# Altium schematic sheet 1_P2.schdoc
size 426 x 304 mm
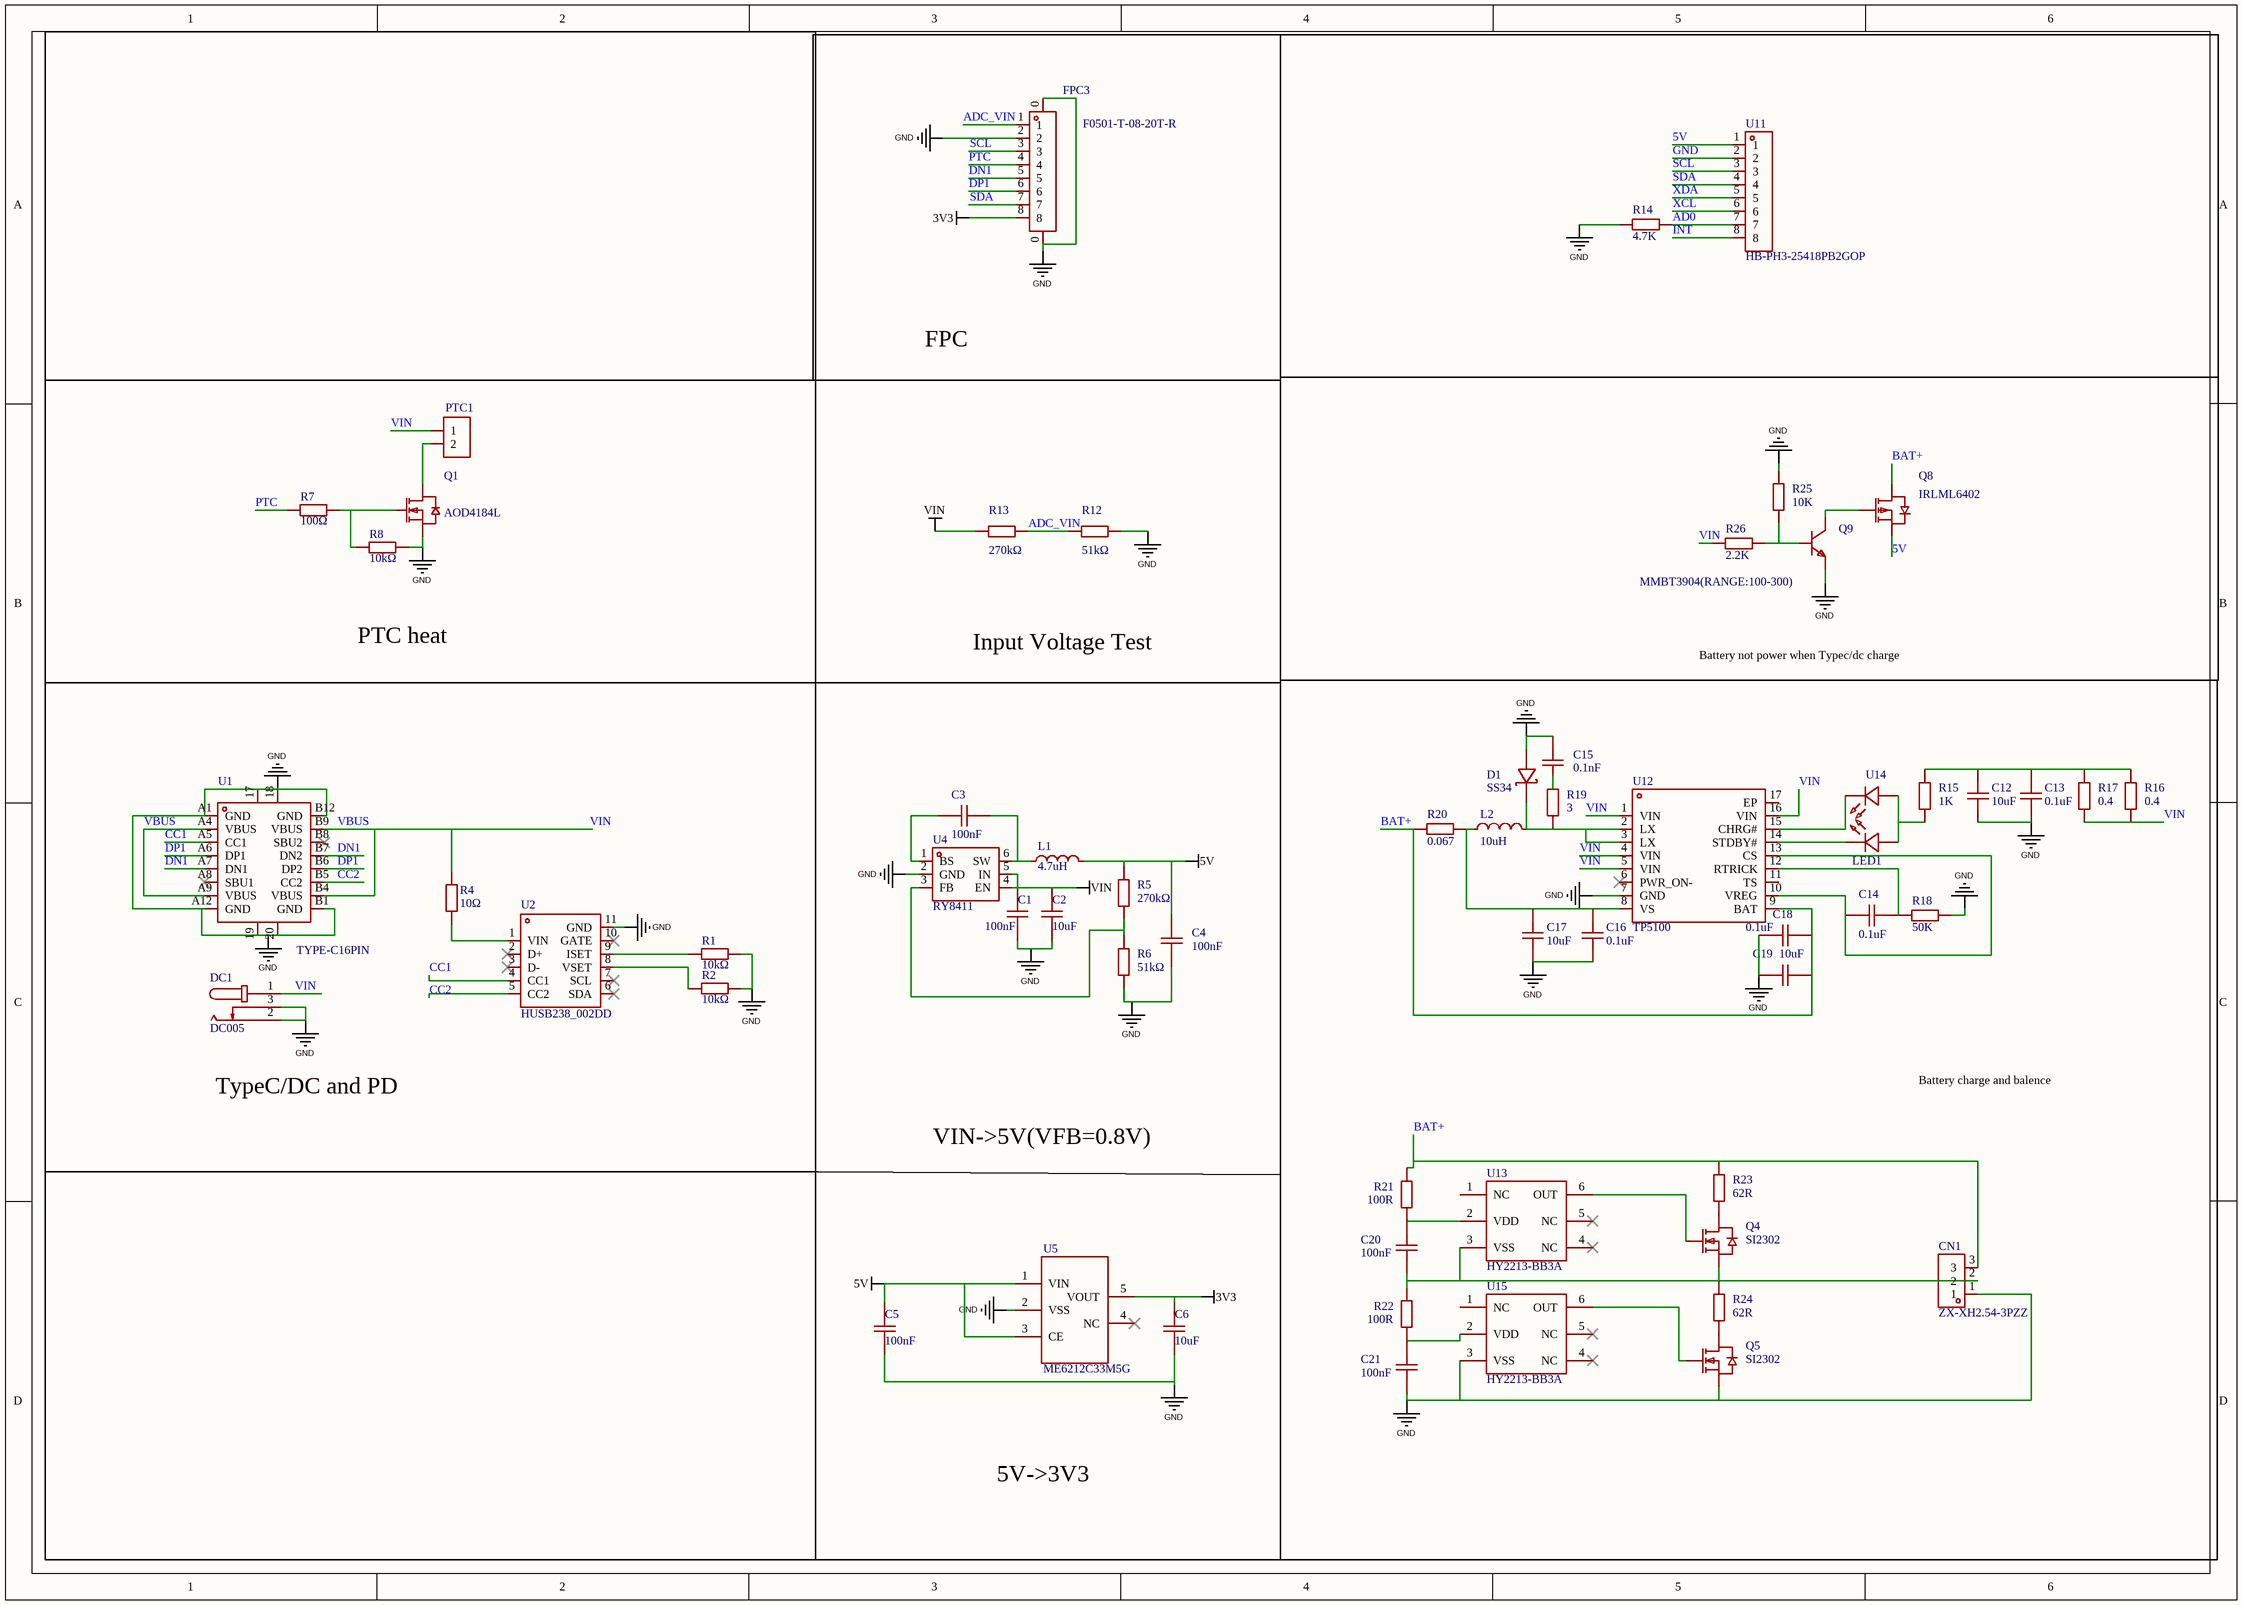
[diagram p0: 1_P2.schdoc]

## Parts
C1  100nF  [C0603]
C2  10uF  [C0603]
C3  100nF  [C0603]
C4  100nF  [C0603]
C5  100nF  [C0603]
C6  10uF  [C0603]
C12  10uF  [C0603]
C13  0.1uF  [C0603]
C14  0.1uF  [C0603]
C15  0.1nF  [C0603]
C16  0.1uF  [C0603]
C17  10uF  [C0603]
C18  0.1uF  [C0603]
C19  10uF  [C0603]
C20  100nF  [C0603]
C21  100nF  [C0603]
CN1  ZX-XH2.54-3PZZ  [CONN-TH_3P-P2.54_2501S-3P]
D1  SS34  [SMA_L4.3-W2.6-LS5.2-RD]
DC1  DC005  [DC-IN-TH_DC005]
FPC3  F0501-T-08-20T-R  [FPC-SMD_8P-P0.50_L4.4-W9.6]
L1  4.7uH  [IND-SMD_L3.5-W3.0]
L2  10uH  [L0603]
LED1  XL-1608SURC-06  [LED0603-RD_RED]  (value not drawn)
PTC1  (no value)  [HDR-TH_2P-P2.54-V-F]
Q1  AOD4184L  [TO-252-2_L6.6-W6.1-P4.57-LS9.9-TL-CW]
Q4  SI2302  [SOT-23-3_L2.9-W1.3-P1.90-LS2.4-BR]
Q5  SI2302  [SOT-23-3_L2.9-W1.3-P1.90-LS2.4-BR]
Q8  IRLML6402  [SOT-23-3_L2.9-W1.3-P1.90-LS2.4-BR]
Q9  MMBT3904(RANGE:100-300)  [SOT-23-3_L2.9-W1.3-P1.90-LS2.4-BR]
R1  10kΩ  [R0603]
R2  10kΩ  [R0603]
R4  10Ω  [R0603]
R5  270kΩ  [R0603]
R6  51kΩ  [R0603]
R7  100Ω  [R0603]
R8  10kΩ  [R0603]
R12  51kΩ  [R0603]
R13  270kΩ  [R0603]
R14  4.7K  [R0603]
R15  1K  [R0603]
R16  0.4  [R0603]
R17  0.4  [R0603]
R18  50K  [R0603]
R19  3  [R0603]
R20  0.067  [R0603]
R21  100R  [R0603]
R22  100R  [R0603]
R23  62R  [R0603]
R24  62R  [R0603]
R25  10K  [R0603]
R26  2.2K  [R0603]
U1  TYPE-C16PIN  [USB-C-SMD_TYPE-C16PIN]
U2  HUSB238_002DD  [DFN-10_L3.0-W3.0-P0.50-BL-EP2.5]
U4  RY8411  [SOT-23-6_L2.9-W1.6-P0.95-LS2.8-TL]
U5  ME6212C33M5G  [SOT-23-5_L3.0-W1.7-P0.95-LS2.8-BL]
U11  HB-PH3-25418PB2GOP  [HDR-TH_8P-P2.54-V-M]
U12  TP5100  [TQFN-16_L4.0-W4.0-P0.65-BL-EP]
U13  HY2213-BB3A  [SOT-23-6_L2.9-W1.6-P0.95-LS2.8-BR]
U14  42-51/GHC-YW2X2K/3T  [LED-SMD_L1.6-W0.8-FD_GREEN-1]  (value not drawn)
U15  HY2213-BB3A  [SOT-23-6_L2.9-W1.6-P0.95-LS2.8-BR]

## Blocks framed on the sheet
FPC: FPC3
Battery not power when Typec/dc charge: Q8 Q9 R14 R25 R26 U11
PTC heat: PTC1 Q1 R7 R8
Input Voltage Test: R12 R13
TypeC/DC and PD: DC1 R1 R2 R4 U1 U2
Battery charge and balence: C12-C21 CN1 D1 L2 LED1 Q4 Q5 R15-R24 U12-U15

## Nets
3V3: C6.1 FPC3.8 U5.5(VOUT)
5V: C4.1 C5.1 L1.2 Q8.2(S) R5.2 U5.1(VIN) U5.3(CE) U11.1
GND: C1.2 C2.2 C4.2 C5.2 C6.2 C12.1 C13.1 C15.2 C16.1 C17.1 C18.2 C19.2 C21.1 CN1.1 D1.2(A) DC1.2 DC1.3 FPC3.0 FPC3.2 Q1.3(S) Q5.2(S) Q9.2(E) R1.2 R2.2 R6.1 R8.2 R12.2 R14.1 R18.2 R25.2 U1.17 U1.18 U1.19 U1.20 U1.A1(GND) U1.A12(GND) U1.B1(GND) U1.B12(GND) U2.11(GND) U4.2(GND) U5.2(VSS) U11.2 U12.7(GND) U15.3(VSS)
VBUS: C1.1 C2.1 DC1.1 PTC1.1 R4.2 R13.1 R16.1 R17.1 R26.1 U1.A4(VBUS) U1.A9(VBUS) U1.B4(VBUS) U1.B9(VBUS) U4.4(EN) U4.5(IN) U12.1(VIN) U12.4(VIN) U12.5(VIN) U12.16(VIN)  [also labelled VIN]
AD0: R14.2 U11.7
ADC_VIN: FPC3.1 R12.1 R13.2
BAT+: C18.1 C19.1 CN1.3 Q8.3(D) R20.1 R21.2 R23.2 U12.9(BAT)
CC1: U1.A5(CC1) U2.4(CC1)
CC2: U1.B5(CC2) U2.5(CC2)
DN1: FPC3.5 U1.A7(DN1) U1.B7(DN2)
DP1: FPC3.6 U1.A6(DP1) U1.B6(DP2)
INT: U11.8
PTC: FPC3.4 R7.1
SCL: FPC3.3 U11.3
SDA: FPC3.7 U11.4
XCL: U11.6
XDA: U11.5
NetC3_1: C3.1 U4.1(BS)
NetC3_2: C3.2 L1.1 U4.6(SW)
NetC12_2: C12.2 C13.2 R15.2 R16.2 R17.2
NetC14_1: C14.1 U12.10(VREG) U12.13(CS)
NetC14_2: C14.2 R18.1 U12.12(RTRICK)
NetC15_1: C15.1 R19.2
NetC16_2: C16.2 C17.2 L2.1 R20.2 U12.8(VS)
NetC20_1: C20.1 CN1.2 Q4.2(S) R22.2 R24.2 U13.3(VSS)
NetC20_2: C20.2 R21.1 U13.2(VDD)
NetC21_2: C21.2 R22.1 U15.2(VDD)
NetD1_1: D1.1(K) L2.2 R19.1 U12.2(LX) U12.3(LX)
NetLED1_1: LED1.1(K) U12.14(STDBY#)
NetLED1_2: LED1.2(A) R15.1 U14.1(A)
NetPTC1_2: PTC1.2 Q1.2(D)
NetQ1_1: Q1.1(G) R7.2 R8.1
NetQ4_1: Q4.1(G) U13.6(OUT)
NetQ4_3: Q4.3(D) R23.1
NetQ5_1: Q5.1(G) U15.6(OUT)
NetQ5_3: Q5.3(D) R24.1
NetQ8_1: Q8.1(G) Q9.3(C)
NetQ9_1: Q9.1(B) R25.1 R26.2
NetR1_1: R1.1 U2.9(ISET)
NetR2_1: R2.1 U2.8(VSET)
NetR4_1: R4.1 U2.1(VIN)
NetR5_1: R5.1 R6.2 U4.3(FB)
NetU12_15: U12.15(CHRG#) U14.2(C)

Not connected (* = marked no-connect by the designer): U1 A8(SBU1)* B8(SBU2)*; U2 2(D+)* 3(D-)* 6(SDA)* 7(SCL)* 10(GATE)*; U5 4(NC)*; U12 6(PWR_ON-)* 11(TS) 17(EP); U13 1(NC) 4(NC)* 5(NC)*; U15 1(NC) 4(NC)* 5(NC)*

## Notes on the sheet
- VIN->5V(VFB=0.8V)
- 5V->3V3

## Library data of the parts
C1 C3-C5 = CGA0603X7R104K500JT: Manufacturer: HRE(芯声); Symbol: CapAcitance; Add into BOM: yes; Tolerance: ±10%; Voltage Rated: 50V; Temperature Coefficient: X7R
C2 C6 = CL10A106KP8NNNC: Manufacturer: SAMSUNG(三星); Symbol: CapAcitance; Add into BOM: yes; Tolerance: ±10%; Voltage Rated: 10V; Temperature Coefficient: X5R
C12-C21 = CAP_0603: Symbol: CapAcitance; Convert to PCB: yes
CN1 = ZX-XH2.54-3PZZ: Manufacturer: Megastar(兆星); Add into BOM: yes; Pins Structure: 1x3P; Pitch: 2.5mm; Reference Series: XH; Number of PINs Per Row: 3; Rated Current: 3A; Rated Voltage (Max): 250V; Plastic Material: PA66; Flame Retardant Rating: UL94V-0; Z-Height of the Board: 7mm; X-Length of Bottom Edge on Board (Spacing Line): 10mm; Y-Width of Bottom Edge on Board: 5.9mm
D1 = SS34_C8678: Manufacturer: MDD(辰达半导体); Add into BOM: yes; Diode Configuration: 独立式; Forward Voltage (Vf@If): 550mV@3A; Reverse Voltage (Vr): 40V; Rectified Current: 3A; Reverse Leakage Current (Ir): 500uA@40V
DC1 = DC005: Manufacturer: SHOU HAN(首韩); Symbol: DC005_C431533; Add into BOM: yes; Connector Type: DC电源插座; Inside Contact Diameter: 2mm; Outside Contact Diameter: 6.3mm; Current Rating (Max): 500mA; Voltage Rating (Max): 30V
FPC3 = F0501-T-08-20T-R: Manufacturer: XFCN(兴飞); Add into BOM: yes; Locking Feature: 抽屉式; Number of Contacts: 8P; Pitch: 0.5mm
L1 = CD32-4R7M 4.7UH: Manufacturer: DMBJ(振宝佳); Add into BOM: yes; Tolerance: ±20%; Rated Current: 1.5A; DC Resistance (DCR): 137mΩ
L2 = L_0603: Symbol: SDFL1608S100KTF; Add into BOM: yes
LED1 = XL-1608SURC-06: Manufacturer: XINGLIGHT(成兴光); Add into BOM: yes; Illumination Color: 红色; Voltage - Forward(Vf): 2.3V; Power(Watts): 50mW; Forward Current: 20mA; Wavelength - Dominant: 620nm~630nm; Peak Wavelength: 625nm; Lens Color: 无色透明透镜; Luminous Intensity: 225mcd; Viewing Angle: 120°; Mounting Sytle: 正贴
PTC1 = HDR-F_2.54_1x2P: Manufacturer: BOOMELE(博穆精密); Manufacturer Part: 2.54-1*2P母; Symbol: Header-Female-2.54_1x2; Convert to PCB: yes
Q1 = AOD4184L: Manufacturer: AOS; Add into BOM: yes; Type: 1个N沟道; Drain Source Voltage (Vdss): 40V; Continuous Drain Current (Id): 50A; Drain Source On Resistance (RDS(on)@Vgs,Id): 8mΩ@10V,20A; Power Dissipation (Pd): 50W; Gate Threshold Voltage (Vgs(th)@Id): 3V@250uA
Q4 Q5 = SI2302_C2891732: Manufacturer: YONGYUTAI(永裕泰); Add into BOM: yes; Type: 1个N沟道; Drain Source Voltage (Vdss): 20V; Continuous Drain Current (Id): 3A; Drain Source On Resistance (RDS(on)@Vgs,Id): 50mΩ@4.5V,3A; Power Dissipation (Pd): 1W; Gate Threshold Voltage (Vgs(th)@Id): 1V@250uA; Total Gate Charge (Qg@Vgs): 60nC@4.5V; Input Capacitance (Ciss@Vds): 300pF@10V; Reverse Transfer Capacitance (Crss@Vds): 80pF@10V
Q8 = IRLML6402_C518785: Manufacturer: HUASHUO(华朔); Add into BOM: yes; Type: 1个P沟道; Drain Source Voltage (Vdss): 20V; Continuous Drain Current (Id): 4.9A; Drain Source On Resistance (RDS(on)@Vgs,Id): 45mΩ@4.5V,4.9A; Power Dissipation (Pd): 1.31W; Gate Threshold Voltage (Vgs(th)@Id): 400mV@250uA; Total Gate Charge (Qg@Vgs): 14.3nC@4.5V; Input Capacitance (Ciss@Vds): 1.2nF@15V; Reverse Transfer Capacitance (Crss@Vds): 151pF@15V
Q9 = MMBT3904(RANGE:100-300): Manufacturer: CJ(江苏长电/长晶); Add into BOM: yes; Transistor Type: NPN; Collector Current (Ic): 200mA; Collector-Emitter Breakdown Voltage (Vceo): 40V; Power Dissipation (Pd): 200mW; DC Current Gain (hFE@Ic,Vce): 100@10mA,1V; Transition Frequency (fT): 300MHz; Collector Cut-Off Current (Icbo): 100nA; Collector-Emitter Saturation Voltage (VCE(sat)@Ic,Ib): 300mV@50mA,5mA
R1 R2 R8 = 0603WAF1002T5E: Manufacturer: UNI-ROYAL(厚声); Symbol: 电阻; Add into BOM: yes; Tolerance: ±1%; Power(Watts): 100mW; Overload Voltage (Max): 75V; Temperature Coefficient: ±100ppm/℃
R4 = 0603WAF100JT5E: Manufacturer: UNI-ROYAL(厚声); Symbol: 电阻; Add into BOM: yes; Tolerance: ±1%; Power(Watts): 100mW; Overload Voltage (Max): 75V; Temperature Coefficient: ±400ppm/℃
R5 = FRC0603F2703TS: Manufacturer: FOJAN(富捷); Symbol: 电阻; Add into BOM: yes; Tolerance: ±1%; Power(Watts): 100mW; Overload Voltage (Max): 75V; Temperature Coefficient: ±100ppm/℃
R6 R12 = 0603WAF5102T5E: Manufacturer: UNI-ROYAL(厚声); Symbol: 电阻; Add into BOM: yes; Tolerance: ±1%; Power(Watts): 100mW; Overload Voltage (Max): 75V; Temperature Coefficient: ±100ppm/℃
R7 = 0603WAF1000T5E: Manufacturer: UNI-ROYAL(厚声); Symbol: 电阻; Add into BOM: yes; Tolerance: ±1%; Power(Watts): 100mW; Overload Voltage (Max): 75V; Temperature Coefficient: ±200ppm/℃
R13 = 0603WAF2703T5E: Manufacturer: UNI-ROYAL(厚声); Symbol: 电阻; Add into BOM: yes; Tolerance: ±1%; Power(Watts): 100mW; Overload Voltage (Max): 75V; Temperature Coefficient: ±100ppm/℃
R14-R26 = Res_0603: Symbol: 电阻; Convert to PCB: yes
U1 = TYPE-C16PIN: Manufacturer: SHOU HAN(首韩); Symbol: TYPE-C16PIN母座 板上四脚三次MOLDING; Add into BOM: yes; Connector Type: Type-C; Gender: 母; Number of Contacts: 16P; Number of Ports: 1; Current Rating - Power (Max): 3A; Rated Voltage (Max): 30V; Connect-Disconnect Life: 1万次; Core Colour: 黑色
U2 = HUSB238_002DD: Manufacturer: Hynetek(慧能泰); Symbol: HUSB238-002D; Add into BOM: yes
U4 = RY8411_C2935411: Manufacturer: RYCHiP(蕊源); Add into BOM: yes
U5 = ME6212C33M5G: Manufacturer: MICRONE(南京微盟); Add into BOM: yes; Output Type: 固定; Maximum Input Voltage: 6V; Output Voltage: 3.3V; MAX Output Current: 350mA; Power Supply Rejection Ratio (PSRR): 65dB; Dropout Voltage: 260mV@(200mA); Output Polarity: 正极; Number of Outputs: 1
U11 = HB-PH3-25418PB2GOP: Manufacturer: HANBO(汉博); Add into BOM: yes; Pin Structure: 1x8P; Pitch: 2.54mm; Circluar Pins/Square Pins: 方针; Current Rating (Max): 3A; Voltage Rating (Max): 250V; Soldering Temperature(Max): 260℃
U12 = TP5100: Manufacturer: TOPPOWER(南京拓微); Symbol: TP5100_C379389; Add into BOM: yes
U13 U15 = HY2213-BB3A: Manufacturer: HYCON(宏康); Add into BOM: yes
U14 = 42-51/GHC-YW2X2K/3T: Manufacturer: EVERLIGHT(亿光); Add into BOM: yes; Emitted Color: 翠绿色; Dominant Wavelength: 520nm~535nm; Luminous Intensity: 2850mcd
